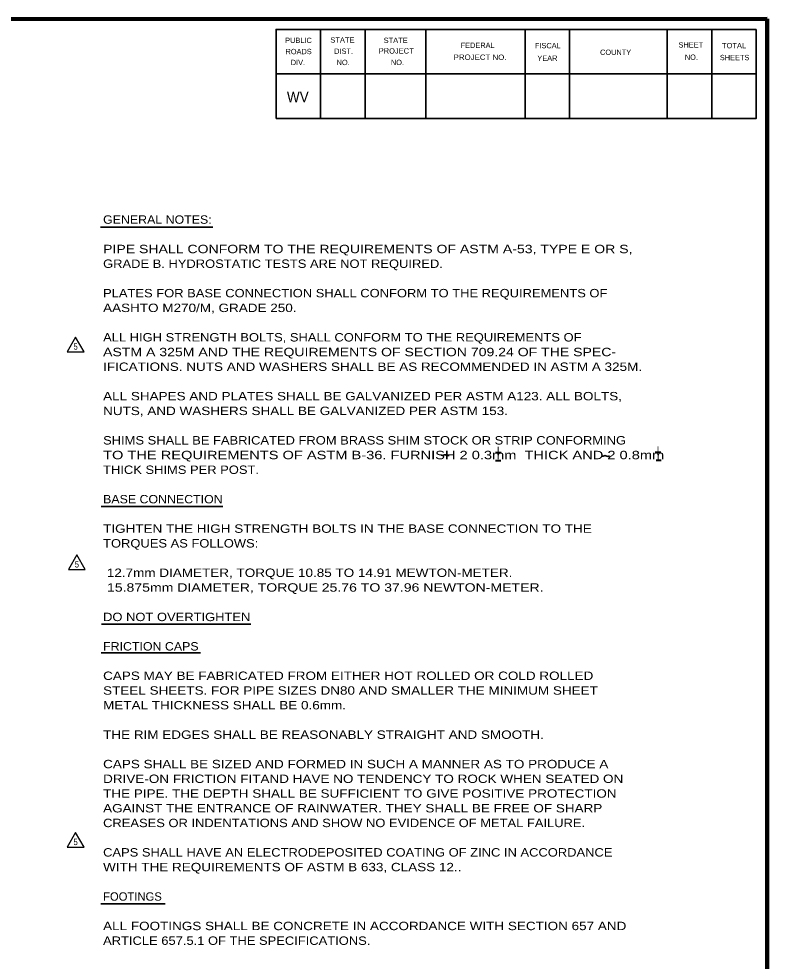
# Model space of a CAD drawing. Extents: x 11 to 867, y -284 to 260.
# Drawn here: x 646.4 to 860, y -14.9 to 254 of the extents above; entities that cross this region are included whole.
import ezdxf
from ezdxf.enums import TextEntityAlignment as Align

# ---------------------------------------------------------------- set-up
doc = ezdxf.new("R2010")
doc.units = 0
doc.header["$LTSCALE"] = 1.2
doc.layers.add('1', color=7, linetype='Continuous', lineweight=53)
doc.layers.add('61', color=7, linetype='Continuous', lineweight=35)

msp = doc.modelspace()

# ---------------------------------------------------------------- linework, layer by layer
at = {"layer": '1', "lineweight": 158}
msp.add_line((860.008, -272.101), (860.008, 254), dxfattribs=at)
at = {"layer": '1', "lineweight": 13}
msp.add_line((860.008, -272.101), (860.008, 254), dxfattribs=at)
at = {"layer": '1', "lineweight": 35}
for p, q in [((669.739, 194.559), (701.796, 194.559)), ((669.912, 114.801), (704.625, 114.801)), ((669.973, 81.234), (712.636, 81.234)), ((669.917, 73.065), (698.235, 73.065)), ((669.793, 1.434), (688.198, 1.434))]:
    msp.add_line(p, q, dxfattribs=at)
at = {"layer": '1', "lineweight": 158}
msp.add_lwpolyline([(860.008, 254), (68.308, 253.9), (68.408, -272.101)], dxfattribs=at)
at = {"layer": '1', "lineweight": 25}
for points in [[(662.6, 163.156), (660.2, 158.999), (665, 158.999)], [(662.941, 101.002), (660.541, 96.845), (665.341, 96.845)], [(662.6, 21.772), (660.2, 17.615), (665, 17.615)]]:
    msp.add_lwpolyline(points, close=True, dxfattribs=at)
at = {"layer": '1', "lineweight": 35}
for points in [[(766.915, 129.483), (767.394, 129.428), (767.892, 129.576), (768.426, 129.428), (769.053, 129.354), (769.218, 129.428)], [(812.705, 129.276), (813.185, 129.221), (813.682, 129.368), (814.216, 129.221), (814.843, 129.147), (815.009, 129.221)]]:
    msp.add_spline(points, degree=3, dxfattribs=at)
at = {"layer": '61'}
for p, q in [((732.508, 251), (732.508, 225.6)), ((745.208, 251), (745.208, 225.6)), ((762.608, 251), (762.608, 225.6)), ((790.908, 251), (790.908, 225.6)), ((803.608, 251), (803.608, 225.6)), ((831.508, 251), (831.508, 225.6)), ((844.208, 251), (844.208, 225.6)), ((856.908, 238.3), (719.808, 238.3))]:
    msp.add_line(p, q, dxfattribs=at)
for points in [[(856.908, 251), (719.808, 251), (719.808, 225.6)], [(856.908, 251), (856.908, 225.6), (719.808, 225.6)]]:
    msp.add_lwpolyline(points, dxfattribs=at)

# ---------------------------------------------------------------- texts
at = {"layer": '1'}
for s, height, width, p in [('WV', 3.048, 0.95, (722.908, 230.2)), ('GENERAL NOTES:', 2.4, 1.1, (670.437, 195.518)), ('PIPE SHALL CONFORM TO THE REQUIREMENTS OF ASTM A-53, TYPE E OR S, ', 2.4, 1.25, (670.437, 187.118)), ('GRADE B. HYDROSTATIC TESTS ARE NOT REQUIRED.', 2.4, 1.15, (670.437, 182.918)), ('PLATES FOR BASE CONNECTION SHALL CONFORM TO THE REQUIREMENTS OF', 2.4, 1.15, (670.437, 174.518)), ('AASHTO M270/M, GRADE 250.', 2.4, 1.2, (670.437, 170.318)), ('ALL HIGH STRENGTH BOLTS, SHALL CONFORM TO THE REQUIREMENTS OF', 2.4, 1.15, (670.437, 161.918)), ('ASTM A 325M AND THE REQUIREMENTS OF SECTION 709.24 OF THE SPEC-', 2.4, 1.25, (670.437, 157.718)), ('IFICATIONS. NUTS AND WASHERS SHALL BE AS RECOMMENDED IN ASTM A 325M.', 2.4, 1.2, (670.437, 153.518)), ('ALL SHAPES AND PLATES SHALL BE GALVANIZED PER ASTM A123. ALL BOLTS,', 2.4, 1.2, (670.437, 145.118)), ('NUTS, AND WASHERS SHALL BE GALVANIZED PER ASTM 153.', 2.4, 1.2, (670.437, 140.918)), ('SHIMS SHALL BE FABRICATED FROM BRASS SHIM STOCK OR STRIP CONFORMING', 2.4, 1.15, (670.437, 132.518)), ('TO THE REQUIREMENTS OF ASTM B-36. FURNISH 2 0.3mm  THICK AND 2 0.8mm ', 2.4, 1.3, (670.437, 128.318)), ('THICK SHIMS PER POST.', 2.4, 1.15, (670.437, 124.118)), ('BASE CONNECTION', 2.4, 1.1, (670.437, 115.718)), ('TIGHTEN THE HIGH STRENGTH BOLTS IN THE BASE CONNECTION TO THE', 2.4, 1.2, (670.437, 107.318)), ('TORQUES AS FOLLOWS:', 2.4, 1.15, (670.437, 103.118)), (' 12.7mm DIAMETER, TORQUE 10.85 TO 14.91 MEWTON-METER.', 2.4, 1.2, (670.437, 94.718)), (' 15.875mm DIAMETER, TORQUE 25.76 TO 37.96 NEWTON-METER.', 2.4, 1.25, (670.437, 90.518)), ('DO NOT OVERTIGHTEN', 2.4, 1.15, (670.437, 82.118)), ('FRICTION CAPS', 2.4, 1.1, (670.437, 73.718)), ('CAPS MAY BE FABRICATED FROM EITHER HOT ROLLED OR COLD ROLLED', 2.4, 1.2, (670.437, 65.318)), ('STEEL SHEETS. FOR PIPE SIZES DN80 AND SMALLER THE MINIMUM SHEET', 2.4, 1.2, (670.437, 61.118)), ('METAL THICKNESS SHALL BE 0.6mm.', 2.4, 1.2, (670.437, 56.918)), ('THE RIM EDGES SHALL BE REASONABLY STRAIGHT AND SMOOTH.', 2.4, 1.2, (670.437, 48.518)), ('CAPS SHALL BE SIZED AND FORMED IN SUCH A MANNER AS TO PRODUCE A', 2.4, 1.2, (670.437, 40.118)), ('DRIVE-ON FRICTION FITAND HAVE NO TENDENCY TO ROCK WHEN SEATED ON', 2.4, 1.2, (670.437, 35.918)), ('THE PIPE. THE DEPTH SHALL BE SUFFICIENT TO GIVE POSITIVE PROTECTION', 2.4, 1.2, (670.437, 31.718)), ('AGAINST THE ENTRANCE OF RAINWATER. THEY SHALL BE FREE OF SHARP', 2.4, 1.2, (670.437, 27.518)), ('CREASES OR INDENTATIONS AND SHOW NO EVIDENCE OF METAL FAILURE.', 2.4, 1.15, (670.437, 23.318)), ('CAPS SHALL HAVE AN ELECTRODEPOSITED COATING OF ZINC IN ACCORDANCE', 2.4, 1.15, (670.437, 14.918)), ('WITH THE REQUIREMENTS OF ASTM B 633, CLASS 12..', 2.4, 1.2, (670.437, 10.718)), ('ALL FOOTINGS SHALL BE CONCRETE IN ACCORDANCE WITH SECTION 657 AND', 2.4, 1.2, (670.437, -6.082)), ('ARTICLE 657.5.1 OF THE SPECIFICATIONS.', 2.4, 1.15, (670.437, -10.282))]:
    msp.add_text(s, height=height, dxfattribs=dict(at, width=width)).set_placement(p)
for s, height, width, p in [('5', 1.8, 0.9, (662.6, 159.573)), ('+', 4.8, 0.55, (783.224, 127.875)), ('+', 4.8, 0.55, (828.863, 127.975)), ('5', 1.8, 0.9, (662.941, 97.419)), ('5', 1.8, 0.9, (662.6, 18.19))]:
    msp.add_text(s, height=height, dxfattribs=dict(at, width=width)).set_placement(p, align=Align.CENTER)
for p in [(783.224, 126.044), (829.029, 126.144)]:
    msp.add_text('-', height=4.8, dxfattribs=at).set_placement(p, align=Align.CENTER)
msp.add_text('FOOTINGS', height=2.4, dxfattribs=at).set_placement((670.437, 2.318))
at = {"layer": '61'}
for s, height, rotation, p in [('PUBLIC', 1.525, 0.033, (722.408, 247.1)), ('ROADS', 1.525, 0.124, (722.508, 243.9)), ('DIST.', 1.525, 0.056, (736.408, 244)), ('FEDERAL', 1.523, 0.007, (772.508, 245.7)), ('FISCAL', 1.525, 359.942, (793.708, 245.6)), ('COUNTY', 1.523, 0.069, (812.308, 243.7)), ('SHEET', 1.525, 0.059, (834.708, 245.8)), ('DIV.', 1.525, 359.932, (724.008, 240.8)), ('YEAR', 1.523, 0.105, (794.408, 242)), ('SHEETS', 1.523, 359.959, (846.508, 242.2))]:
    msp.add_text(s, height=height, rotation=rotation, dxfattribs=at).set_placement(p)
for s, rotation, width, p in [('STATE', 0.059, 1.05, (735.308, 247.2)), ('STATE', 0.059, 1.05, (750.508, 247.1)), ('PROJECT', 359.908, 1.05, (749.108, 244.1)), ('TOTAL', 359.926, 1.05, (847.108, 245.6)), ('NO.', 359.852, 0.9, (737.108, 240.8)), ('NO.', 0.225, 0.9, (752.608, 240.8)), ('PROJECT NO.', 359.922, 1.1, (770.508, 242.3)), ('NO.', 359.852, 0.9, (836.508, 242.3))]:
    msp.add_text(s, height=1.525, rotation=rotation, dxfattribs=dict(at, width=width)).set_placement(p)

doc.saveas('drawing.dxf')
